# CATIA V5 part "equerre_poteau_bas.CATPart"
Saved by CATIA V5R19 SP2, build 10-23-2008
Part number: Pièce4
Bounding box of the stored display mesh (mm): x -42.309 to 197.892, y -20.222 to 20, z -50.635 to 109.499
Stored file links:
  C:\Users\augus\OneDrive\Documents\Augustin\ECL\EPSA\Ergonomie\banc ergo\catia\equerre_poteau_bas.CATPart
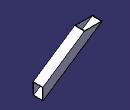
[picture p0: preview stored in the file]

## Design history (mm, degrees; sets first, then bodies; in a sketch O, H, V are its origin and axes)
Body1 (main body)
  DatumSurface1
  DatumCurve1
  DatumSurface2
  Sketch1 on face of DatumSurface1, origin (197.8919, 0, 0), H (0, 1, 0), V (0, 0, 1)
    point P1 (0, -50.5014)
    reference projected line E1 (-40, -50.5014) -> (40, -50.5014) from edge of DatumCurve1
    coincidence: P1 V, P1 E1
  Plane1: stored without definition
  DatumCurve2
  Sketch2 on face of DatumSurface2, origin (0, 0, 109.4986), H (1, 0, 0), V (0, 1, 0)
    point P1 (-42.1081, 0)
    reference intersected line E1 through (0, 0) direction (-1, 0) from Plane1
    point P2 (-42.1081, 0)
    reference projected line E2 (-42.1081, -20) -> (-42.1081, 20) from edge of DatumCurve2
    coincidence: E1 P1, P2 H, P1 P2, P1 E2
  Line1: type PtPt, FirstPoint Sketch1, SecondPoint Sketch2.P1
  Sketch3 on zx-plane, origin (0, 0, 0), H (-1, 0, 0), V (0, 0, 1)
    point P1 (-72.282, 33.2386)
    reference projected line E1 (-197.8919, -50.5014) -> (15.2169, 91.5712) from Line1
    line L1 (-92.2635, 19.9176) -> (-197.8919, -50.5014)
    point P2 (-92.2635, 19.9176)
    point P3 (-197.8919, -50.5014)
    reference projected point E2 (-197.8919, -50.5014) from Sketch1
    line L2 (-72.282, 33.2386) -> (42.1081, 109.4986)
    point P4 (42.1081, 109.4986)
    reference projected point E3 (42.1081, 109.4986) from Sketch2.P1
    coincidence: P1 E1, P3 E2, P4 E3
  Plane2: type Normal, Curve Line1, RefPoint Sketch3.P2
  Sketch4 on Plane2, origin (51.6874, 0.438, -40.9466), H (-0.0031, -1, -0.0046), V (0.5547, -0.0056, 0.832)
    line L1 (-19.9692, 113.151) -> (20.0308, 113.151)
    line L2 (20.0308, 113.151) -> (20.0308, 73.151)
    line L3 (20.0308, 73.151) -> (-19.9692, 73.151)
    line L4 (-19.9692, 73.151) -> (-19.9692, 113.151)
    reference projected point E1 (0.0308, 73.151) from Sketch3.P2
    reference projected point E2 (0.0308, 73.151) from Sketch3.P2
    line L5 (-18.4692, 111.651) -> (18.5308, 111.651)
    line L6 (18.5308, 111.651) -> (18.5308, 74.651)
    line L7 (18.5308, 74.651) -> (-18.4692, 74.651)
    line L8 (-18.4692, 74.651) -> (-18.4692, 111.651)
    length L3 = 40
    length L2 = 40
    distance E2 L2 = 20
    distance L6 L2 = 1.5
    distance L7 L3 = 1.5
    distance L8 L4 = 1.5
    distance L1 L5 = 1.5
    horizontal: L1 H, L3 H, L5 H, L7 H
    vertical: L2 V, L4 V, L6 V, L8 V
    coincidence: E1 L3
  DatumSurface3
  DatumPoint1
  Plane3: type OffsetPt, RefPlane DatumSurface3, RefPoint DatumPoint1
  DatumSurface4
  Plane4: type OffsetPt, RefPlane DatumSurface4, RefPoint Sketch1
  DatumSurface5
  Pad1: profile Sketch4, direction (-0.8321, 0, 0.5547), up to Plane3, opposite side up to Plane4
